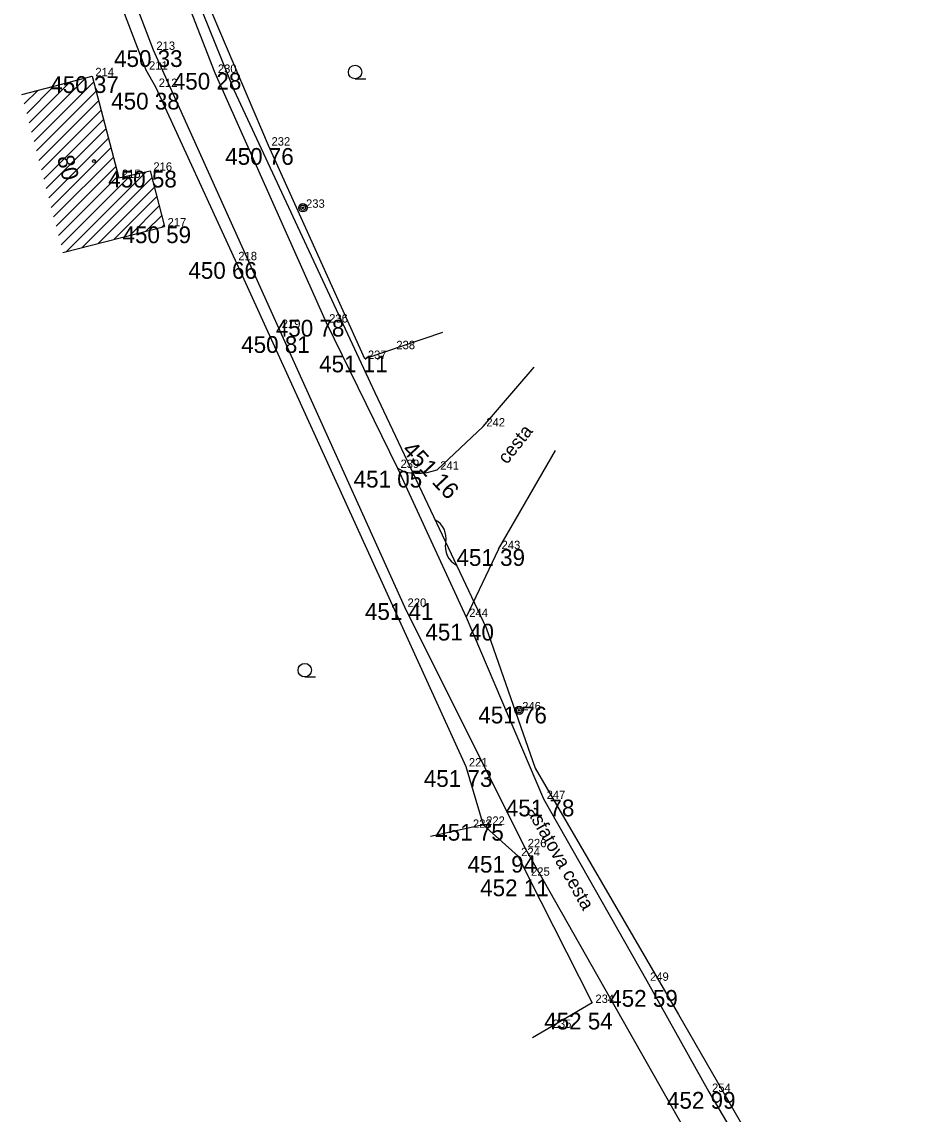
# Model space of a CAD drawing. Extents: x -559180 to -551373, y -1076947 to -1072071.
# Drawn here: x -553829.3 to -553776.6, y -1075034.3 to -1074969.2 of the extents above; entities that cross this region are included whole.
import ezdxf

# ---------------------------------------------------------------- set-up
doc = ezdxf.new("R2010")
doc.units = 0
for name, color, linetype in [('12_PLOTY', 7, 'Continuous'), ('13_PLOTY', 7, 'Continuous'), ('14_BUDOVY', 7, 'Continuous'), ('17_KOMUNIKACE', 7, 'Continuous'), ('1_VODA_ZN', 7, 'Continuous'), ('20_EL_ZN', 7, 'Continuous'), ('30_SDEL_ZN', 7, 'Continuous'), ('32', 7, 'Continuous'), ('3_BODY', 7, 'Continuous'), ('45_ZN_KULTURY', 7, 'Continuous'), ('47_ZN_STAV_OBJ$', 7, 'Continuous'), ('52_POPIS_UCELOVY', 7, 'Continuous'), ('54_C_POPISNA', 7, 'Continuous'), ('6_VYSKY', 7, 'Continuous')]:
    doc.layers.add(name, color=color, linetype=linetype)

# ---------------------------------------------------------------- blocks, each defined once
blk = doc.blocks.new('POINT_DISPLAY')
blk.add_line((0, 0), (0, 0))
blk = doc.blocks.new('SLB')
at = {"layer": '20_EL_ZN'}
for radius in [0.25, 0.158, 0.05]:
    blk.add_circle((0, 0), radius, dxfattribs=at)
blk = doc.blocks.new('BZ')
at = {"layer": '47_ZN_STAV_OBJ$'}
blk.add_circle((0, 0), 0.0875, dxfattribs=at)
blk = doc.blocks.new('ZAHRAD')
at = {"layer": '45_ZN_KULTURY'}
blk.add_line((0, 0), (0.65, 0.003), dxfattribs=at)
blk.add_circle((0, 0.403), 0.403, dxfattribs=at)
blk = doc.blocks.new('SDEP')
at = {"layer": '30_SDEL_ZN'}
for centre, radius, start, end in [((0.75, -1.001), 1.251, 53.1529, 126.84692), ((2.25, 1), 1.25, 233.13001, 306.86981)]:
    blk.add_arc(centre, radius, start, end, dxfattribs=at)

msp = doc.modelspace()

# ---------------------------------------------------------------- linework, layer by layer
at = {"layer": '12_PLOTY'}
for p, q in [((-553814.56, -1074976.55), (-553821.89, -1074959.27)), ((-553823.71, -1074967.24), (-553821.87, -1074972.02)), ((-553821.87, -1074972.02), (-553821.29, -1074973.05)), ((-553821.29, -1074973.05), (-553816.54, -1074983.39)), ((-553808.81, -1074989.28), (-553814.56, -1074976.55)), ((-553816.54, -1074983.39), (-553802.78, -1075013.6)), ((-553804.175, -1074987.699), (-553808.81, -1074989.28)), ((-553802.78, -1075013.6), (-553801.75, -1075017.08)), ((-553801.75, -1075017.08), (-553804.89, -1075017.784)), ((-553801.75, -1075017.08), (-553799.66, -1075018.95)), ((-553799.66, -1075018.95), (-553799.07, -1075020.12)), ((-553799.07, -1075020.12), (-553795.23, -1075027.71)), ((-553795.23, -1075027.71), (-553798.804, -1075029.798))]:
    msp.add_line(p, q, dxfattribs=at)
at = {"layer": '13_PLOTY'}
for p, q in [((-553822.25, -1074959.25), (-553816.63, -1074973.23)), ((-553816.63, -1074973.23), (-553808.21, -1074991.29)), ((-553808.21, -1074991.29), (-553801.57, -1075005.32)), ((-553801.57, -1075005.32), (-553798.65, -1075013.7)), ((-553798.65, -1075013.7), (-553790.09, -1075028.39)), ((-553790.09, -1075028.39), (-553785.2, -1075036.88))]:
    msp.add_line(p, q, dxfattribs=at)
at = {"layer": '14_BUDOVY'}
for p, q in [((-553829.274, -1074973.505), (-553825.07, -1074972.41)), ((-553825.07, -1074972.41), (-553823.49, -1074978.48)), ((-553823.49, -1074978.48), (-553821.61, -1074978.05)), ((-553821.61, -1074978.05), (-553820.76, -1074981.37)), ((-553826.822, -1074982.922), (-553820.76, -1074981.37))]:
    msp.add_line(p, q, dxfattribs=at)
at = {"layer": '17_KOMUNIKACE'}
for p, q in [((-553822.41, -1074960.22), (-553817.76, -1074972.21)), ((-553824.2, -1074963.65), (-553821.43, -1074970.84)), ((-553821.43, -1074970.84), (-553813.95, -1074987.43)), ((-553817.76, -1074972.21), (-553811.12, -1074987.11)), ((-553811.12, -1074987.11), (-553806.86, -1074995.79)), ((-553813.95, -1074987.43), (-553806.44, -1075004.07)), ((-553801.74, -1074993.31), (-553798.696, -1074989.774)), ((-553804.49, -1074995.89), (-553801.74, -1074993.31)), ((-553800.83, -1075000.63), (-553797.434, -1074994.741)), ((-553806.86, -1074995.79), (-553802.76, -1075004.68)), ((-553800.83, -1075000.63), (-553802.76, -1075004.68)), ((-553806.44, -1075004.07), (-553799.27, -1075018.42)), ((-553802.76, -1075004.68), (-553798.14, -1075015.54)), ((-553798.14, -1075015.54), (-553791.97, -1075026.39)), ((-553799.27, -1075018.42), (-553789.43, -1075035.77)), ((-553791.97, -1075026.39), (-553788.27, -1075033.02)), ((-553788.27, -1075033.02), (-553776.62, -1075052.76))]:
    msp.add_line(p, q, dxfattribs=at)
msp.add_lwpolyline([(-553806.86, -1074995.79), (-553806.398, -1074996.033), (-553806.084, -1074996.086), (-553805.776, -1074996.1), (-553805.452, -1074996.093), (-553805.078, -1074996.05), (-553804.49, -1074995.89)], dxfattribs=at)
at = {"layer": '32'}
for p, q in [((-553828.836, -1074975.188), (-553826.406, -1074972.758)), ((-553828.69, -1074975.749), (-553825.449, -1074972.509)), ((-553828.544, -1074976.31), (-553824.982, -1074972.748)), ((-553829.128, -1074974.066), (-553828.318, -1074973.256)), ((-553828.982, -1074974.627), (-553827.362, -1074973.007)), ((-553828.398, -1074976.871), (-553824.836, -1074973.31)), ((-553828.251, -1074977.432), (-553824.69, -1074973.871)), ((-553828.105, -1074977.993), (-553824.544, -1074974.432)), ((-553827.959, -1074978.554), (-553824.398, -1074974.993)), ((-553827.813, -1074979.115), (-553824.252, -1074975.554)), ((-553827.667, -1074979.676), (-553824.106, -1074976.115)), ((-553827.521, -1074980.237), (-553823.96, -1074976.676)), ((-553827.375, -1074980.798), (-553823.814, -1074977.237)), ((-553827.229, -1074981.359), (-553823.668, -1074977.798)), ((-553827.083, -1074981.92), (-553823.521, -1074978.359)), ((-553826.937, -1074982.481), (-553822.771, -1074978.315)), ((-553826.618, -1074982.87), (-553821.854, -1074978.106)), ((-553825.668, -1074982.626), (-553821.504, -1074978.463)), ((-553824.717, -1074982.383), (-553821.36, -1074979.026)), ((-553823.767, -1074982.14), (-553821.216, -1074979.589)), ((-553822.816, -1074981.896), (-553821.072, -1074980.152)), ((-553821.866, -1074981.653), (-553820.928, -1074980.715)), ((-553820.915, -1074981.41), (-553820.784, -1074981.278))]:
    msp.add_line(p, q, dxfattribs=at)

# ---------------------------------------------------------------- block references
at = {"layer": '1_VODA_ZN'}
for p in [(-553821.43, -1074970.84), (-553821.87, -1074972.02), (-553825.07, -1074972.41), (-553817.76, -1074972.21), (-553821.29, -1074973.05), (-553814.56, -1074976.55), (-553821.61, -1074978.05), (-553823.49, -1074978.48), (-553812.5, -1074980.26), (-553820.76, -1074981.37), (-553816.54, -1074983.39), (-553811.12, -1074987.11), (-553813.95, -1074987.43), (-553807.11, -1074988.7), (-553808.81, -1074989.28), (-553801.74, -1074993.31), (-553806.86, -1074995.79), (-553804.49, -1074995.89), (-553800.83, -1075000.63), (-553806.44, -1075004.07), (-553802.76, -1075004.68), (-553799.6, -1075010.25), (-553802.78, -1075013.6), (-553798.14, -1075015.54), (-553801.75, -1075017.08), (-553802.54, -1075017.26), (-553799.27, -1075018.42), (-553799.66, -1075018.95), (-553799.07, -1075020.12), (-553791.97, -1075026.39), (-553795.23, -1075027.71), (-553797.78, -1075029.2), (-553788.27, -1075033.02)]:
    msp.add_blockref('POINT_DISPLAY', p, dxfattribs=at)
at = {"layer": '20_EL_ZN'}
for p in [(-553812.5, -1074980.26), (-553799.6, -1075010.25)]:
    msp.add_blockref('SLB', p, dxfattribs=at)
at = {"layer": '30_SDEL_ZN', "xscale": 1.0000000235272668, "yscale": 1.0000000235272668, "rotation": -64.67321530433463}
msp.add_blockref('SDEP', (-553804.621, -1074998.873), dxfattribs=at)
at = {"layer": '32'}
msp.add_blockref('POINT_DISPLAY', (-553829.274, -1074973.505), dxfattribs=at)
at = {"layer": '45_ZN_KULTURY'}
for p in [(-553809.386, -1074972.565), (-553812.39, -1075008.256)]:
    msp.add_blockref('ZAHRAD', p, dxfattribs=at)
at = {"layer": '47_ZN_STAV_OBJ$'}
msp.add_blockref('BZ', (-553824.972, -1074977.474), dxfattribs=at)

# ---------------------------------------------------------------- texts
at = {"layer": '3_BODY'}
for s, p in [(' 213', (-553821.43, -1074970.84)), (' 211', (-553821.87, -1074972.02)), (' 214', (-553825.07, -1074972.41)), (' 230', (-553817.76, -1074972.21)), (' 212', (-553821.29, -1074973.05)), (' 232', (-553814.56, -1074976.55)), (' 215', (-553823.49, -1074978.48)), (' 216', (-553821.61, -1074978.05)), (' 233', (-553812.5, -1074980.26)), (' 217', (-553820.76, -1074981.37)), (' 218', (-553816.54, -1074983.39)), (' 219', (-553813.95, -1074987.43)), (' 236', (-553811.12, -1074987.11)), (' 238', (-553807.11, -1074988.7)), (' 237', (-553808.81, -1074989.28)), (' 242', (-553801.74, -1074993.31)), (' 239', (-553806.86, -1074995.79)), (' 241', (-553804.49, -1074995.89)), (' 243', (-553800.83, -1075000.63)), (' 220', (-553806.44, -1075004.07)), (' 244', (-553802.76, -1075004.68)), (' 246', (-553799.6, -1075010.25)), (' 221', (-553802.78, -1075013.6)), (' 247', (-553798.14, -1075015.54)), (' 223', (-553802.54, -1075017.26)), (' 222', (-553801.75, -1075017.08)), (' 224', (-553799.66, -1075018.95)), (' 226', (-553799.27, -1075018.42)), (' 225', (-553799.07, -1075020.12)), (' 249', (-553791.97, -1075026.39)), (' 234', (-553795.23, -1075027.71)), (' 235', (-553797.78, -1075029.2)), (' 254', (-553788.27, -1075033.02))]:
    msp.add_text(s, height=0.5, dxfattribs=at).set_placement(p)
at = {"layer": '52_POPIS_UCELOVY'}
for s, rotation, p in [('cesta', 51.62226, (-553800.323, -1074995.607)), ('asfatova cesta', 299.55961, (-553799.175, -1075016.244))]:
    msp.add_text(s, height=0.8, rotation=rotation, dxfattribs=at).set_placement(p)
at = {"layer": '54_C_POPISNA'}
msp.add_text('80', height=1, rotation=284.59013, dxfattribs=at).set_placement((-553827.182, -1074977.265))
at = {"layer": '6_VYSKY'}
for s, p in [('450 33', (-553823.771, -1074971.858)), ('450 37', (-553827.575, -1074973.41)), ('450 28', (-553820.265, -1074973.21)), ('450 38', (-553823.941, -1074974.397)), ('450 76', (-553817.138, -1074977.696)), ('450 58', (-553824.115, -1074979.05)), ('450 59', (-553823.265, -1074982.37)), ('450 66', (-553819.336, -1074984.499)), ('450 78', (-553814.117, -1074987.946)), ('450 81', (-553816.182, -1074988.922)), ('451 11', (-553811.533, -1074990.079)), ('451 05', (-553809.474, -1074996.954)), ('451 39', (-553803.335, -1075001.63)), ('451 41', (-553808.799, -1075004.851)), ('451 40', (-553805.192, -1075006.082)), ('451 76', (-553802.032, -1075011.031)), ('451 73', (-553805.285, -1075014.819)), ('451 78', (-553800.39, -1075016.576)), ('451 75', (-553804.601, -1075018.025)), ('451 94', (-553802.675, -1075019.932)), ('452 11', (-553801.922, -1075021.339)), ('452 59', (-553794.22, -1075027.937)), ('452 54', (-553798.1, -1075029.293)), ('452 99', (-553790.775, -1075034.02))]:
    msp.add_text(s, height=1, dxfattribs=at).set_placement(p)
msp.add_text('451 16', height=1, rotation=313.31532, dxfattribs=at).set_placement((-553806.636, -1074994.762))

doc.saveas('drawing.dxf')
